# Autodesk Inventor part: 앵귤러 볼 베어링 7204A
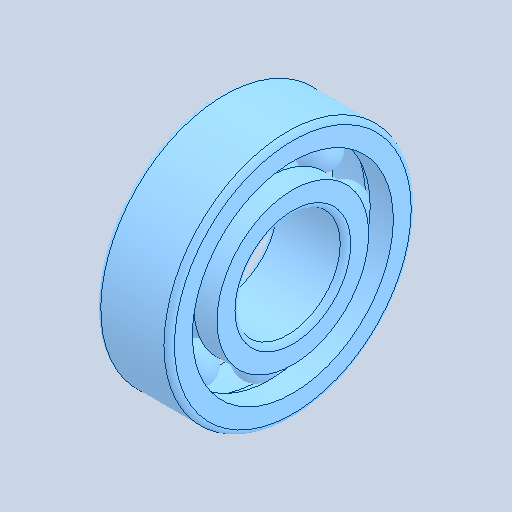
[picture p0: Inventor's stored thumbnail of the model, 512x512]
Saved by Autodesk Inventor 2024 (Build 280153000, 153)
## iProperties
Created: 2024-11
Part Number: 앵귤러 볼 베어링 7204A
Material: 강철, 연강
Description: 앵귤러 콘택트 볼 베어링
Document SubType Name: Modeling
Designer: user
Density: 7.85 g/cm^3
Appearance: 기본값
Author: jhkim
Sending System: Autodesk Inventor 2025
Preprocessor: ST-DEVELOPER v20
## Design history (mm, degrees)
node "앵귤러 볼 제어링 7204A1"
node "솔리드1"
node "솔리드2"
node "솔리드3"
node "솔리드4"
node "솔리드5"
node "솔리드6"
node "솔리드7"
node "솔리드8"
node "솔리드9"
node "솔리드10"
body "Solid1"
node "Solid1:1"
node "Solid1:2"
node "Solid1:3"
node "Solid1:4"
node "Solid1:5"
node "Solid1:6"
node "Solid1:7"
node "Solid1:8"
node "Solid1:9"
